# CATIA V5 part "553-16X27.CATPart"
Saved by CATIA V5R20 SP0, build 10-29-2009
Part number: 553-16X27
Definition: NONE
Nomenclature: 553-16X27
Source: Unknown
Description: 553-16X27
Bounding box of the stored display mesh (mm): x 0 to 27, y -13 to 13, z -13 to 13
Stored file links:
  C:\Users\Utente\Desktop\IO LAVORO\3D X SITO CF\X SITO\PLASTICA\553\553-16X27.CATPart
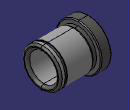
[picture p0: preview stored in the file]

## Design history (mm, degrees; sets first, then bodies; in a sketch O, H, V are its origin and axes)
Body1 "553-16X27" (main body)
  Solid1: solid without history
